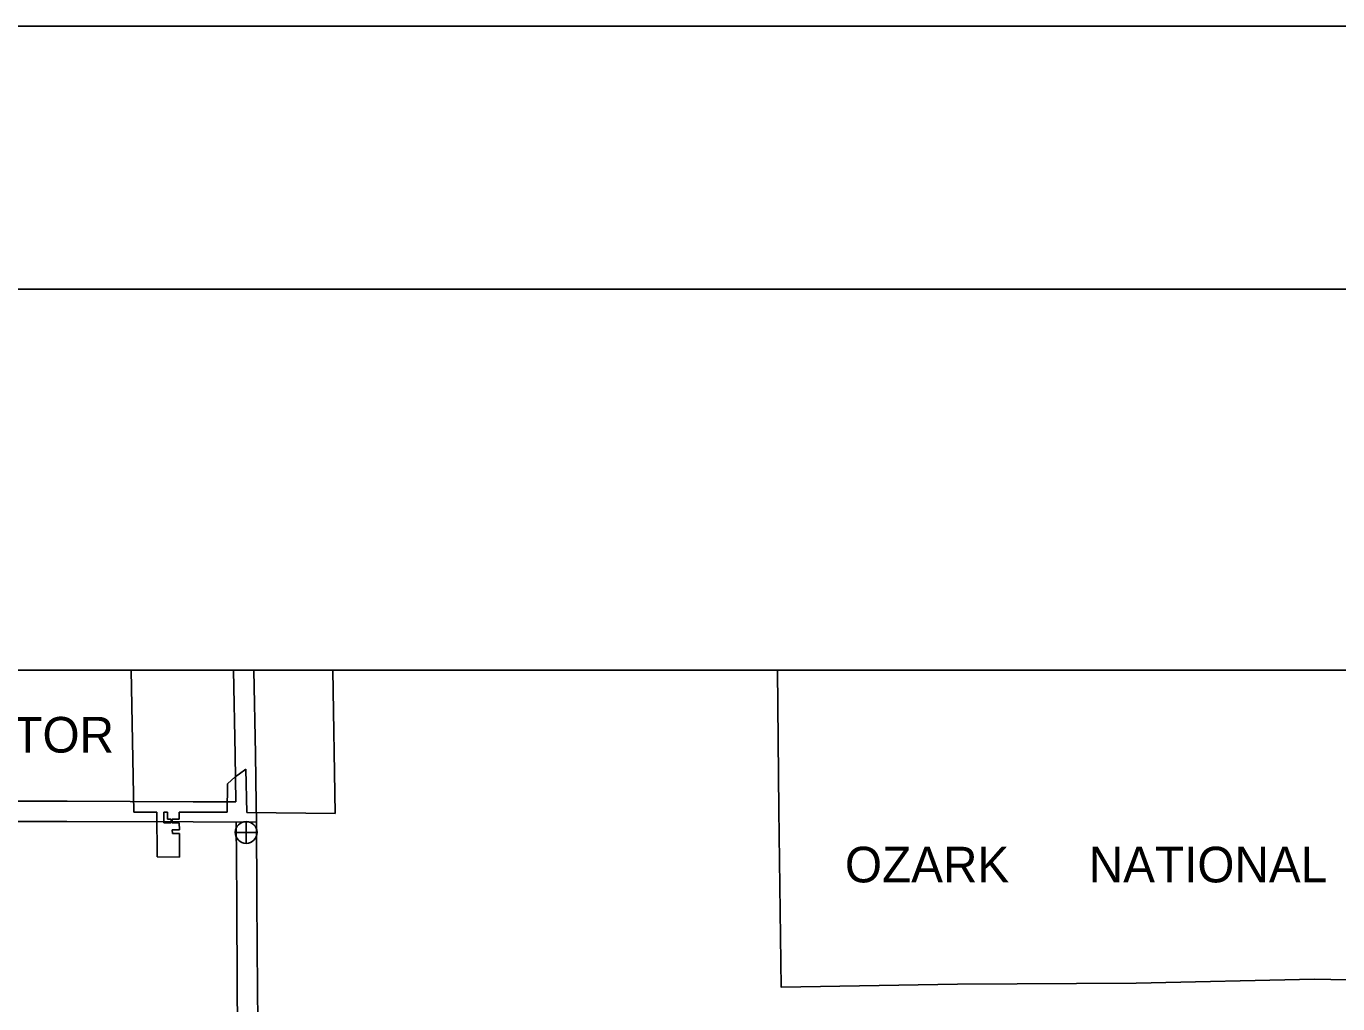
# Model space of a CAD drawing. Extents: x 1374139 to 1377472, y 1168351 to 1170484.
# Drawn here: x 1374734 to 1374928.1, y 1170339.4 to 1170484.1 of the extents above; entities that cross this region are included whole.
import ezdxf

# ---------------------------------------------------------------- set-up
doc = ezdxf.new("R2010")
doc.units = 0
for name, color, linetype in [('26', 7, 'Continuous'), ('6', 7, 'Continuous'), ('Default', 7, 'Continuous')]:
    doc.layers.add(name, color=color, linetype=linetype)

msp = doc.modelspace()

# ---------------------------------------------------------------- linework, layer by layer
at = {"layer": '26'}
msp.add_line((1374138.81, 1170484.1), (1377472.14, 1170484.1), dxfattribs=at)
for points in [[(1374138.74, 1170484.1), (1377472.14, 1170484.1), (1377472.14, 1168350.73), (1374138.74, 1168350.73)], [(1374299.15, 1170388.77), (1375028.55, 1170388.77), (1375028.55, 1169604.28), (1374299.15, 1169604.28)]]:
    msp.add_lwpolyline(points, close=True, dxfattribs=at)
at = {"layer": '6'}
msp.add_line((1374262.81, 1170445.16), (1377424.61, 1170445.16), dxfattribs=at)
at = {"layer": 'Default'}
for p, q in [((1374749.51, 1170388.77), (1374779.34, 1170388.77)), ((1374749.86, 1170367.75), (1374749.51, 1170388.77)), ((1374779.34, 1170388.77), (1374779.71, 1170367.53)), ((1374765.51, 1170373.42), (1374764.9, 1170372.95)), ((1374766.46, 1170374.08), (1374765.51, 1170373.42)), ((1374766.61, 1170367.7), (1374766.46, 1170374.08)), ((1374763.73, 1170371.91), (1374763.7, 1170367.71)), ((1374764.9, 1170372.95), (1374763.73, 1170371.91)), ((1374753.28, 1170367.74), (1374749.86, 1170367.75)), ((1374753.34, 1170361.1), (1374753.28, 1170367.74)), ((1374754.86, 1170367.73), (1374754.33, 1170367.73)), ((1374754.33, 1170367.73), (1374754.34, 1170366.16)), ((1374754.87, 1170366.68), (1374754.86, 1170367.73)), ((1374759.94, 1170367.72), (1374756.61, 1170367.73)), ((1374756.61, 1170367.73), (1374756.62, 1170366.68)), ((1374763.7, 1170367.71), (1374759.94, 1170367.72)), ((1374779.71, 1170367.53), (1374766.61, 1170367.7)), ((1374754.34, 1170366.16), (1374755.39, 1170366.16)), ((1374755.39, 1170366.68), (1374754.87, 1170366.68)), ((1374755.39, 1170366.16), (1374755.39, 1170366.68)), ((1374756.62, 1170366.68), (1374755.57, 1170366.68)), ((1374755.57, 1170366.68), (1374755.57, 1170366.15)), ((1374755.57, 1170366.15), (1374756.62, 1170366.15)), ((1374756.62, 1170366.15), (1374756.63, 1170365.1)), ((1374766.52, 1170363.11), (1374766.52, 1170366.36)), ((1374756.63, 1170365.1), (1374755.58, 1170365.1)), ((1374755.58, 1170365.1), (1374755.59, 1170364.58)), ((1374755.59, 1170364.58), (1374756.64, 1170364.58)), ((1374756.64, 1170364.58), (1374756.66, 1170361.08)), ((1374764.9, 1170364.73), (1374768.15, 1170364.73)), ((1374756.66, 1170361.08), (1374753.34, 1170361.1))]:
    msp.add_line(p, q, dxfattribs=at)
for points in [[(1374764.63, 1170388.77), (1374764.89, 1170376.24), (1374764.99, 1170369.27)], [(1374767.63, 1170388.77), (1374767.89, 1170376.3), (1374767.99, 1170368.95), (1374767.99, 1170368.52)], [(1374924.7, 1170343.01), (1374898.27, 1170342.41), (1374871.83, 1170342.28), (1374845.74, 1170341.81), (1374845.39, 1170368.05), (1374845.16, 1170388.77)], [(1374764.99, 1170369.27), (1374758.69, 1170369.28), (1374739.99, 1170369.34), (1374728.75, 1170369.37)], [(1374767.99, 1170368.56), (1374768.03, 1170366.87), (1374768.11, 1170354.82), (1374768.19, 1170341.35), (1374768.22, 1170336.91)], [(1374768.03, 1170366.26), (1374758.69, 1170366.28), (1374739.98, 1170366.34), (1374728.74, 1170366.37)], [(1374765.04, 1170366.24), (1374765.11, 1170354.8), (1374765.19, 1170341.33), (1374765.23, 1170336.62)], [(1374951.1, 1170342.46), (1374924.7, 1170343.01)]]:
    msp.add_lwpolyline(points, dxfattribs=at)
msp.add_circle((1374766.52, 1170364.73), 1.62, dxfattribs=at)

# ---------------------------------------------------------------- texts
for s, p in [('HECTOR', (1374717.14, 1170376.55)), ('OZARK      NATIONAL      FOREST', (1374855.17, 1170357.33))]:
    msp.add_text(s, height=5.28, dxfattribs=at).set_placement(p)

doc.saveas('drawing.dxf')
